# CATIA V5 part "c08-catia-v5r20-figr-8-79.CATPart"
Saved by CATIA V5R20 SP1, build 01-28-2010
Part number: Part1
Bounding box of the stored display mesh (mm): x -35 to 35, y -116.369 to 116.369, z 0 to 117.647
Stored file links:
  D:\v5_r20\psrt_files_downloaded\c08-catia-v5r20-prt\c08-catia-v5r20-figr-8-79.CATPart
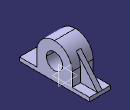
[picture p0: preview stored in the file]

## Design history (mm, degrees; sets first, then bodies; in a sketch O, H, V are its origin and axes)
Body1 (main body)
  Sketch1 on yz-plane, origin (0, 0, 0), H (0, 1, 0), V (0, 0, 1)
    line L1 (0, 0) -> (116.3687, 0)
    point P1 (116.3687, 0)
    line L2 (116.3687, 0) -> (116.3687, 12.5279)
    point P2 (116.3687, 12.5279)
    line L3 (116.3687, 12.5279) -> (58.943, 12.5279)
    point P3 (58.943, 12.5279)
    line L4 (58.943, 12.5279) -> (58.943, 58.7038)
    point P4 (58.943, 58.7038)
    arc A1 centre (0, 58.7038) radius 58.943 from (58.943, 58.7038) to (0, 117.6467) ccw
    point P5 (0, 58.7038)
    point P6 (-58.943, 58.7038)
    line L5 (-58.943, 58.7038) -> (-58.943, 12.5279)
    point P7 (-58.943, 12.5279)
    axis line L6 (0, 0) -> (0, 108.1111)
    point P9 (0, 117.6467)
    point P10 (0, 117.6467)
    point P11 (-58.943, 58.7038)
    arc A2 centre (0, 58.7038) radius 58.943 from (-58.943, 58.7038) to (0, 117.6467) cw
    point P13 (-58.943, 12.5279)
    point P14 (-116.3687, 12.5279)
    line L7 (-116.3687, 12.5279) -> (-58.943, 12.5279)
    point P15 (-116.3687, 0)
    line L8 (-116.3687, 0) -> (-116.3687, 12.5279)
    point P16 (0, 0)
    line L9 (0, 0) -> (-116.3687, 0)
    circle A3 centre (0, 58.7038) radius 27.1825
    horizontal: L1 H, L3 H
    vertical: L2 V, L4 V, L6 V
    tangency: A1 L4, L5 A1
    coincidence: P7 L3, P5 V, L6 P9, P6 P11, O P16, P9 P10, P7 P13
    symmetry: P9 P10 L6, P4 P11 L6, A1 A2 L6, P3 P13 L6, P2 P14 L6, L3 L7 L6, P1 P15 L6, L2 L8 L6, O P16 L6, L1 L9 L6
  Pad1: profile Sketch1, direction (1, 0, 0), length 35, mirrored extent
  Sketch2 on yz-plane, origin (0, 0, 0), H (0, 1, 0), V (0, 0, 1)
    line L1 (116.3687, 12.5279) -> (44.9741, 96.8037)
    point P1 (116.3687, 12.5279)
    point P2 (44.9741, 96.8037)
    reference projected arc E1 centre (0, 58.7038) radius 58.943 from (58.943, 58.7038) to (0, 117.6467) ccw from edge [face of Pad1 | face of Pad1]
    reference projected arc E2 centre (0, 58.7038) radius 58.943 from (58.943, 58.7038) to (0, 117.6467) ccw from edge [face of Pad1 | face of Pad1]
    reference projected point E3 (116.3687, 12.5279) from vertex [face of Pad1 | face of Pad1 | face of Pad1]
    tangency: L1 E1
    coincidence: P2 E2, P1 E3
  Stiffener1: ThicknessValue 15, ExtendedProfile Sketch2, ThicknessTop 0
